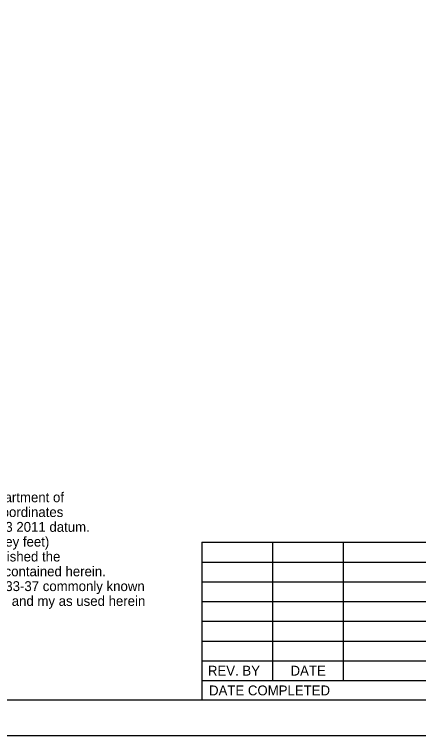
# Model space of a CAD drawing. Extents: x 1.8 to 35.8, y 1.7 to 23.7.
# Drawn here: x 24.34 to 30.08, y 1.72 to 11.94 of the extents above; entities that cross this region are included whole.
import ezdxf

# ---------------------------------------------------------------- set-up
doc = ezdxf.new("R2010")
doc.units = 0
for name, color, linetype in [('SN_X_Public', 7, 'Continuous'), ('SV_X_Mon_Cells_Found', 7, 'Continuous'), ('SV_X_Shot_Marker', 7, 'Continuous')]:
    doc.layers.add(name, color=color, linetype=linetype)

msp = doc.modelspace()

# ---------------------------------------------------------------- linework, layer by layer
at = {"layer": 'SN_X_Public'}
for p, q in [((27.004, 4.461), (27.004, 2.221)), ((27.004, 4.461), (33.808, 4.461)), ((28.004, 4.461), (28.004, 2.501)), ((29.004, 4.461), (29.004, 2.501)), ((27.004, 4.181), (33.808, 4.181)), ((27.004, 3.901), (33.808, 3.901)), ((27.004, 3.621), (33.808, 3.621)), ((27.004, 3.341), (33.808, 3.341)), ((27.004, 3.061), (33.808, 3.061)), ((27.004, 2.781), (33.808, 2.781)), ((27.004, 2.501), (33.808, 2.501))]:
    msp.add_line(p, q, dxfattribs=at)
at = {"layer": 'SV_X_Mon_Cells_Found'}
msp.add_lwpolyline([(1.808, 1.721), (35.808, 1.721), (35.808, 23.721), (1.808, 23.721)], close=True, dxfattribs=at)
at = {"layer": 'SV_X_Shot_Marker'}
msp.add_lwpolyline([(3.308, 23.221), (35.308, 23.221), (35.308, 2.221), (3.308, 2.221)], close=True, dxfattribs=at)

# ---------------------------------------------------------------- texts
at = {"layer": 'SN_X_Public'}
for s, p in [('I, Michael Jay Wilson, P. S. have conducted a survey of the existing conditions for the Ohio Department of', (16.275, 5.029)), ('Transportation in June, 2021.  The results of that survey are contained herein.  The horizontal coordinates', (16.275, 4.819)), ('expressed herein are based on the Ohio State Plane Coordinate System, South Zone on NAD 83 2011 datum.', (16.275, 4.609)), ('The Project Coordinates (US Survey feet) are relative to State Plane Grid Coordinates (US Survey feet)', (16.275, 4.399)), ('by a Project Adjustment Factor multiplier of 1.00009896.  As a part of this project I have reestablished the', (16.275, 4.189)), ('locations of the existing property lines and centerline of existing Right of Way for property takes contained herein.  ', (16.275, 3.979)), ('All of my work contained herein was conducted in accordance with Ohio Administrative Code 4733-37 commonly known', (16.275, 3.769)), ('as "A Minimum Standards for Boundary Surveys in the State of Ohio" unless noted.  The words I and my as used herein', (16.275, 3.559)), ('REV. BY', (27.088, 2.571)), ('DATE', (28.26, 2.571)), ('DATE COMPLETED', (27.104, 2.291))]:
    msp.add_text(s, height=0.14, dxfattribs=at).set_placement(p)

doc.saveas('drawing.dxf')
